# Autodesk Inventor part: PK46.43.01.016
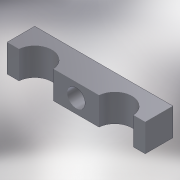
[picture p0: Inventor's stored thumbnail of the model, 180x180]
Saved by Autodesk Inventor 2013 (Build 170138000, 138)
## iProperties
Shininess: 64.0
Length Units: 11269
Angle Units: 11279
Time Units: 11290
Mass Units: 11283
Length Display Precision: 3
Angle Display Precision: 2
Compacted: True
Part Number: PK46.43.01.016
Document SubType Name: Modeling
Created: 2004-12
Material: Сталь высокопрочная низколегированная
Designer: ELarisa
Manufacturer: Standard
Standards Organization: Custom
Density: 7.84 g/cm^3
Density: 0.0
Volumn: 0.0
Area: 0.0
PropertySet Name: Model Information
Control State: 0
Master: False
Checked Out: False
Checked Out Date: 2008-10-09
Last Check In Date: 2008-10-09
Author: ELarisa
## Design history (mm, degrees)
sketch "Эскиз3"
  geometry: L1 (82.501, -4.822)-(82.501, 15.178); L2 (-17.499, 15.178)-(-17.499, -4.822); L3 (82.501, 15.178)-(-17.499, 15.178); L4 (-17.499, -4.822)-(-8.959, -4.822); L5 (15.961, -4.822)-(49.041, -4.822); L6 (73.961, -4.822)-(82.501, -4.822); A1 r 12.5 centre (3.501, -5.822) between (15.961, -4.822) and (-8.959, -4.822); A2 r 12.5 centre (61.501, -5.822) between (73.961, -4.822) and (49.041, -4.822)
  constraints: 12 end point, 4 parallel, 4 point on circle, 3 horizontal, 3 perpendicular, 2 centre point, 2 collinear
  dimensions: "d17" = 100 distance between parallel lines of L1 L2; "d19" = 20 distance of L2.start L2.end; "d20" = 12.5 radius of A1; "d21" = 12.5 radius of A2; "d22" = 58 distance of A2.centre A1.centre; "d23" = 1 distance from line of A1.centre L4; "d24" = 1 distance from line of L6 A2.centre; "d25" = 21 distance from line of L2 A1.centre
extrude "Выдавливание2" new body sketch "Эскиз3" distance "d26" = 20; taper "d27" = 0 deg
sketch "Эскиз4"
  geometry: L1 (0, -20)-(100, -20) reference; L2 (0, 0)-(0, -20) reference; 1 further point
  dimensions: "d28" = 10 distance from line of point (50, -10) L1; "d29" = 50 distance from line of L2 point (50, -10)
hole "Отверстие2" sketch "Эскиз4" diameter "d30" = 13; stored, may be unused: countersink angle "d34" = 90 deg, drill point angle "d36" = 118 deg; dims "d31" = 6, "d32" = 16, "d33" = 2, "d35" = 8
body "Solid1"
